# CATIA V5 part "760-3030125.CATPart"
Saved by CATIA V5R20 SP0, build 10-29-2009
Part number: 760-3030125
Source: Unknown
Property "A": "30.000"
Property "ARTICLENO": "760-3030125"
Property "BOMINFO": "760-3030125"
Property "CODE": "760-3030125"
Property "K": "40.000"
Property "L": "80.000"
Property "LINA": "760-3030125"
Property "NB": "760-3030125"
Property "NBSYN": "$CODE."
Property "NN": "760"
Property "NT": "Key"
Property "SUPPLIER": "CF"
Bounding box of the stored display mesh (mm): x -40 to 40, y 0 to 30, z -15 to 15
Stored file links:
  C:\Users\Utente\Desktop\3D files 760\760-3030125.CATPart
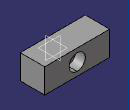
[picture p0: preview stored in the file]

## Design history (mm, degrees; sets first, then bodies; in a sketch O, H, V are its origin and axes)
Body1 "Geometry.1" (main body)
  Solid1 "760-3030125.catpart": solid without history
